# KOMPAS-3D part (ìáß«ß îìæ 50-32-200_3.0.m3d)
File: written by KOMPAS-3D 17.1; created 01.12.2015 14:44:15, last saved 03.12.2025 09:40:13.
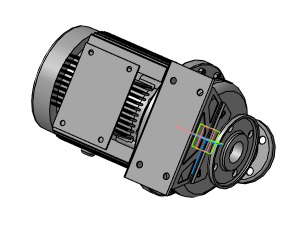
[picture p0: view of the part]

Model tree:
1. Операция без истории:4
